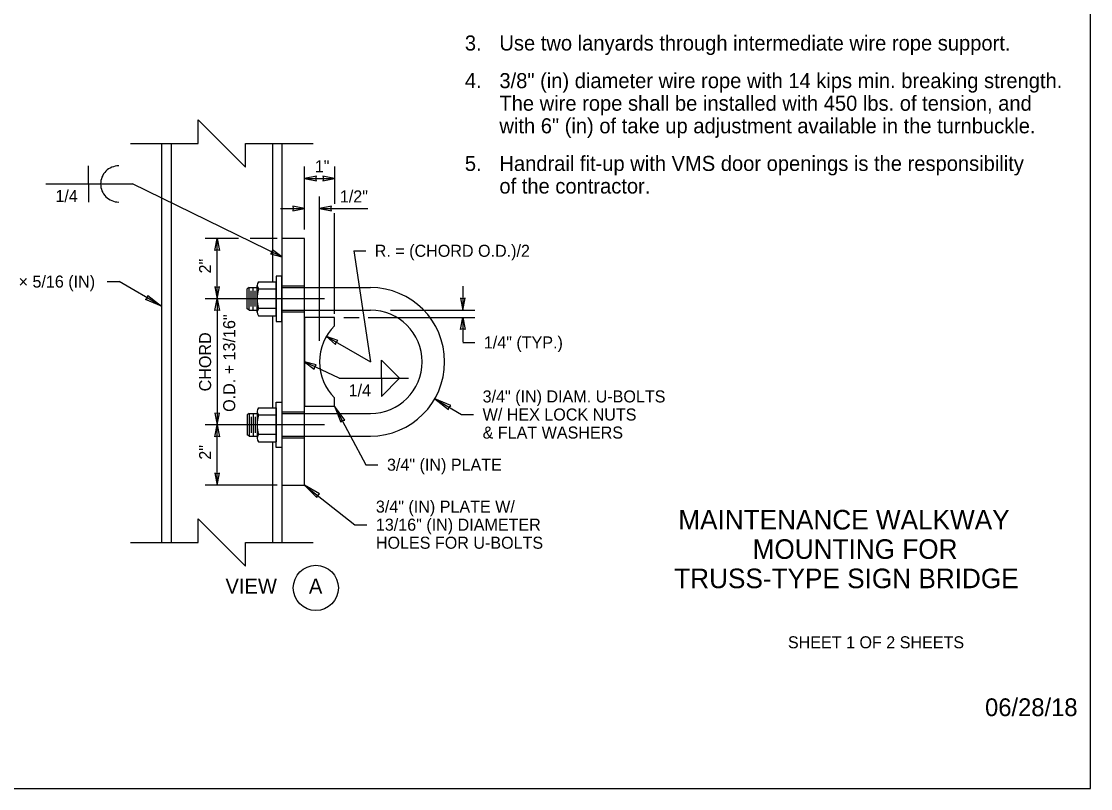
# Model space of a CAD drawing. Extents: x 99862 to 103151, y 100000 to 105076.
# Drawn here: x 101730 to 103151, y 100000 to 101019 of the extents above; entities that cross this region are included whole.
import ezdxf

# ---------------------------------------------------------------- set-up
doc = ezdxf.new("R2010")
doc.units = 0
for name, color, linetype in [('Level 1', 7, 'Continuous'), ('Level 15', 7, 'Continuous'), ('Level 2', 7, 'Continuous'), ('Level 20', 7, 'Continuous'), ('Level 36', 7, 'Continuous'), ('Level 4', 7, 'Continuous'), ('Level 6', 7, 'Continuous'), ('Level 62', 7, 'Continuous'), ('Level 9', 7, 'Continuous')]:
    doc.layers.add(name, color=color, linetype=linetype)

msp = doc.modelspace()

# ---------------------------------------------------------------- linework, layer by layer
at = {"layer": 'Level 1'}
msp.add_lwpolyline([(99862, 99999.5), (103151, 99999.5), (103151, 102075.5), (99862, 102075.5)], close=True, dxfattribs=at)
at = {"layer": 'Level 15'}
for p, q in [((102106.1, 100742.3), (102106.1, 100826.3)), ((102146.1, 100826.3), (102146.1, 100776.3)), ((102076.1, 100705.9), (101877.3, 100802.9)), ((102106.1, 100810.3), (102146.1, 100810.3)), ((102126.1, 100594.6), (102126.1, 100786.3)), ((102074.1, 100770.3), (102106.1, 100770.3)), ((102126.1, 100770.3), (102190, 100770.3)), ((102146.1, 100630.3), (102146.1, 100764.3)), ((102018.4, 100730.3), (101973.9, 100730.3)), ((101989.9, 100650.3), (101989.9, 100730.3)), ((102069.8, 100730.3), (102033.9, 100730.3)), ((102171.4, 100714.1), (102187.4, 100714.1)), ((102171.4, 100714.1), (102193.6, 100566.6)), ((101843.8, 100673.2), (101859.8, 100673.2)), ((101916.1, 100640.7), (101859.8, 100673.2)), ((102316.4, 100667.3), (102316.4, 100635.3)), ((102132.4, 100650.3), (101973.9, 100650.3)), ((101989.9, 100650.3), (101989.9, 100482.8)), ((102220.2, 100635.3), (102332.4, 100635.3)), ((102158.1, 100625.3), (102178.8, 100625.3)), ((102190.8, 100625.3), (102332.4, 100625.3)), ((102316.4, 100625.3), (102316.4, 100593.3)), ((102135.1, 100600.3), (102193.6, 100566.6)), ((102316.4, 100592.3), (102332.4, 100592.3)), ((102152.1, 100544.7), (102106.1, 100566.6)), ((102279.1, 100517.2), (102314.8, 100496.6)), ((102146.1, 100507.8), (102187.7, 100429.9)), ((102314.8, 100496.6), (102330.8, 100496.6)), ((102132.4, 100482.8), (101973.9, 100482.8)), ((101989.9, 100402.8), (101989.9, 100482.8)), ((102187.7, 100429.9), (102203.7, 100429.9)), ((102069.8, 100402.8), (101973.9, 100402.8)), ((102106.1, 100402.8), (102172.9, 100350.2)), ((102172.9, 100350.2), (102188.9, 100350.2))]:
    msp.add_line(p, q, dxfattribs=at)
for points in [[(101874.7, 100856.6), (101964.7, 100856.6), (101964.7, 100887.9), (102027.4, 100825.2), (102027.4, 100856.6), (102117.4, 100856.6)], [(101874.7, 100326.6), (101964.7, 100326.6), (101964.7, 100357.9), (102027.4, 100295.2), (102027.4, 100326.6), (102117.4, 100326.6)]]:
    msp.add_lwpolyline(points, dxfattribs=at)
for points in [[(102106.1, 100810.3), (102121.8, 100807.2), (102121.1, 100810.3), (102121.8, 100813.4)], [(102146.1, 100810.3), (102130.4, 100813.4), (102131.1, 100810.3), (102130.4, 100807.2)], [(102106.1, 100770.3), (102090.4, 100773.4), (102091.1, 100770.3), (102090.4, 100767.2)], [(102126.1, 100770.3), (102141.8, 100767.2), (102141.1, 100770.3), (102141.8, 100773.4)], [(101989.9, 100730.3), (101993, 100714.6), (101989.9, 100715.3), (101986.8, 100714.6)], [(102076.1, 100705.9), (102063.3, 100715.6), (102062.6, 100712.5), (102060.6, 100710.1)], [(101989.9, 100650.3), (101993, 100666), (101989.9, 100665.3), (101986.8, 100666)], [(101916.1, 100640.7), (101894.8, 100649.5), (101897.2, 100651.6), (101897.8, 100654.7)], [(101989.9, 100650.3), (101993, 100634.6), (101989.9, 100635.3), (101986.8, 100634.6)], [(102316.4, 100635.3), (102319.5, 100651), (102316.4, 100650.3), (102313.4, 100651)], [(102316.4, 100625.3), (102319.5, 100609.6), (102316.4, 100610.3), (102313.4, 100609.6)], [(102135.1, 100600.3), (102147.2, 100589.8), (102148.1, 100592.8), (102150.3, 100595.1)], [(102106.1, 100566.6), (102119, 100557), (102119.6, 100560.1), (102121.6, 100562.6)], [(102279.1, 100517.2), (102297.4, 100503.2), (102298, 100506.3), (102300.4, 100508.4)], [(102146.1, 100507.8), (102154.2, 100486.3), (102156.3, 100488.6), (102159.5, 100489.1)], [(101989.9, 100482.8), (101993, 100498.5), (101989.9, 100497.8), (101986.8, 100498.5)], [(101989.9, 100482.8), (101993, 100467.1), (101989.9, 100467.8), (101986.8, 100467.1)], [(101989.9, 100402.8), (101993, 100418.5), (101989.9, 100417.8), (101986.8, 100418.5)], [(102106.1, 100402.8), (102122.2, 100386.4), (102123.2, 100389.4), (102125.9, 100391)]]:
    msp.add_lwpolyline(points, close=True, dxfattribs=at)
at = {"layer": 'Level 2'}
for p, q in [((102146.1, 100625.3), (102106.1, 100625.3)), ((102146.1, 100614.5), (102146.1, 100625.3)), ((102146.1, 100507.8), (102146.1, 100518.6)), ((102106.1, 100507.8), (102146.1, 100507.8))]:
    msp.add_line(p, q, dxfattribs=at)
msp.add_lwpolyline([(102106.1, 100730.3), (102076.1, 100730.3), (102076.1, 100402.8), (102106.1, 100402.8)], close=True, dxfattribs=at)
msp.add_lwpolyline([(102106.1, 100625.3), (102106.1, 100507.8)], dxfattribs=at)
msp.add_arc((102193.6, 100566.6), 67.5, 134.7249, 225.2751, dxfattribs=at)
at = {"layer": 'Level 20'}
for p, q in [((101819, 100802.9), (101819, 100826.9)), ((101762.3, 100802.9), (101877.3, 100802.9)), ((101819, 100802.9), (101819, 100778.9)), ((102208.5, 100544.7), (102208.5, 100568.7)), ((102208.5, 100568.7), (102232.5, 100544.7)), ((102152.1, 100544.7), (102244.4, 100544.7)), ((102208.5, 100544.7), (102208.5, 100520.7)), ((102208.5, 100520.7), (102232.5, 100544.7))]:
    msp.add_line(p, q, dxfattribs=at)
for start, end in [(90.0239, 180.024), (179.976, 269.9761)]:
    msp.add_arc((101859, 100802.9), 24, start, end, dxfattribs=at)
at = {"layer": 'Level 36'}
for p, q in [((101928.6, 100856.6), (101928.6, 100326.6)), ((102063.6, 100856.6), (102063.6, 100672.8)), ((102076.1, 100667.6), (102106.1, 100667.6)), ((102076.1, 100665.3), (102106.1, 100665.3)), ((102076.1, 100635.3), (102106.1, 100635.3)), ((102076.1, 100633.1), (102106.1, 100633.1)), ((102063.6, 100627.8), (102063.6, 100505.3)), ((102076.1, 100500.1), (102106.1, 100500.1)), ((102076.1, 100497.8), (102106.1, 100497.8)), ((102063.6, 100460.3), (102063.6, 100326.6)), ((102076.1, 100467.8), (102106.1, 100467.8)), ((102076.1, 100465.6), (102106.1, 100465.6))]:
    msp.add_line(p, q, dxfattribs=at)
at = {"layer": 'Level 4'}
for p, q in [((102044.7, 100672.8), (102068.4, 100672.8)), ((102068.4, 100627.8), (102068.4, 100672.8)), ((102032.5, 100665.3), (102029.7, 100663.7)), ((102029.7, 100636.9), (102029.7, 100663.7)), ((102032.5, 100665.3), (102043.2, 100665.3)), ((102032.5, 100635.3), (102032.5, 100665.3)), ((102035.2, 100639.9), (102035.2, 100660.8)), ((102037.9, 100635.3), (102037.9, 100665.3)), ((102040.6, 100639.9), (102040.6, 100660.8)), ((102043.2, 100632.5), (102043.2, 100668.1)), ((102068.4, 100663.3), (102044.7, 100663.3)), ((102032.5, 100635.3), (102029.7, 100636.9)), ((102032.5, 100635.3), (102043.2, 100635.3)), ((102068.4, 100637.3), (102044.7, 100637.3)), ((102044.7, 100627.8), (102068.4, 100627.8)), ((102044.7, 100505.3), (102068.4, 100505.3)), ((102068.4, 100505.3), (102068.4, 100460.3)), ((102032.5, 100497.8), (102029.7, 100496.2)), ((102029.7, 100496.2), (102029.7, 100469.4)), ((102032.5, 100497.8), (102043.2, 100497.8)), ((102032.5, 100497.8), (102032.5, 100467.8)), ((102035.2, 100493.3), (102035.2, 100472.4)), ((102037.9, 100497.8), (102037.9, 100467.8)), ((102040.6, 100493.3), (102040.6, 100472.4)), ((102043.2, 100500.6), (102043.2, 100465.1)), ((102068.4, 100495.8), (102044.7, 100495.8)), ((102032.5, 100467.8), (102029.7, 100469.4)), ((102032.5, 100467.8), (102043.2, 100467.8)), ((102068.4, 100469.8), (102044.7, 100469.8)), ((102044.7, 100460.3), (102068.4, 100460.3))]:
    msp.add_line(p, q, dxfattribs=at)
for points in [[(102076.1, 100620.3), (102076.1, 100680.3), (102068.4, 100680.3), (102068.4, 100620.3)], [(102076.1, 100512.8), (102076.1, 100452.8), (102068.4, 100452.8), (102068.4, 100512.8)]]:
    msp.add_lwpolyline(points, close=True, dxfattribs=at)
for centre, radius, start, end in [((102051.5, 100668.1), 8.24, 144.7199, 215.2801), ((102099.9, 100650.3), 56.7, 166.7504, 193.2496), ((102051.5, 100632.6), 8.24, 144.7199, 215.2801), ((102051.5, 100500.6), 8.24, 144.7199, 215.2801), ((102099.9, 100482.8), 56.7, 166.7504, 193.2496), ((102051.5, 100465.1), 8.24, 144.7199, 215.2801)]:
    msp.add_arc(centre, radius, start, end, dxfattribs=at)
at = {"layer": 'Level 6'}
for p, q in [((101916.1, 100856.6), (101916.1, 100326.6)), ((102076.1, 100856.6), (102076.1, 100730.3)), ((102106.1, 100665.3), (102193.6, 100665.3)), ((102106.1, 100635.3), (102193.6, 100635.3)), ((102106.1, 100497.8), (102193.6, 100497.8)), ((102106.1, 100467.8), (102193.6, 100467.8)), ((102076.1, 100402.8), (102076.1, 100326.6))]:
    msp.add_line(p, q, dxfattribs=at)
for radius in [98.7, 68.7]:
    msp.add_arc((102193.6, 100566.6), radius, 270, 90, dxfattribs=at)
at = {"layer": 'Level 9'}
msp.add_circle((102121.1, 100266.2), 30, dxfattribs=at)

# ---------------------------------------------------------------- texts
at = {"layer": 'Level 15'}
msp.add_text('06/28/18', height=23.62, dxfattribs=at).set_placement((103010.7, 100095.8))
at = {"layer": 'Level 20'}
for s, height, p in [('3.', 20, (102319.2, 100980.2)), ('Use two lanyards through intermediate wire rope support.', 20, (102365.1, 100980.2)), ('4.', 20, (102319.2, 100930.2)), ('3/8" (in) diameter wire rope with 14 kips min. breaking strength.', 20, (102365.1, 100930.2)), ('The wire rope shall be installed with 450 lbs. of tension, and', 20, (102365.1, 100900.2)), ('with 6" (in) of take up adjustment available in the turnbuckle.', 20, (102365.1, 100870.2)), ('1"', 16, (102119.7, 100818.3)), ('5.', 20, (102319.2, 100820.2)), ('Handrail fit-up with VMS door openings is the responsibility', 20, (102365.1, 100820.2)), ('of the contractor. ', 20, (102365.1, 100790.2)), ('1/4', 16, (101774.9, 100778.9)), ('1/2"', 16, (102153, 100778.3)), ('R. = (CHORD O.D.)/2', 16, (102199.4, 100706.1)), ('TS6×4 × 5/16 (IN)', 16, (101656.4, 100665.2)), ('1/4" (TYP.)', 16, (102344.4, 100584.3)), ('1/4', 16, (102164.7, 100520.7)), ('3/4" (IN) DIAM. U-BOLTS', 16, (102342.8, 100512.6)), ('W/ HEX LOCK NUTS', 16, (102342.8, 100488.6)), ('& FLAT WASHERS', 16, (102342.8, 100464.6)), ('3/4" (IN) PLATE', 16, (102215.7, 100421.9)), ('3/4" (IN) PLATE W/', 16, (102200.9, 100366.2)), ('13/16" (IN) DIAMETER', 16, (102200.9, 100342.2)), ('HOLES FOR U-BOLTS', 16, (102200.9, 100318.2)), ('VIEW', 20, (102001, 100258.6)), ('A', 20, (102111.9, 100258.6))]:
    msp.add_text(s, height=height, dxfattribs=at).set_placement(p)
for s, p in [('2"', (101981.9, 100684)), ('O.D. + 13/16"', (102013.9, 100500.1)), ('CHORD', (101981.9, 100527.3)), ('2"', (101981.9, 100436.5))]:
    msp.add_text(s, height=16, rotation=90, dxfattribs=at).set_placement(p)
at = {"layer": 'Level 62'}
for s, height, p in [('MAINTENANCE WALKWAY', 26, (102602.9, 100343.8)), ('MOUNTING FOR', 26, (102701.7, 100304.8)), ('TRUSS-TYPE SIGN BRIDGE', 26, (102597.5, 100265.8)), ('SHEET 1 OF 2 SHEETS', 16, (102748.6, 100185.9))]:
    msp.add_text(s, height=height, dxfattribs=at).set_placement(p)

doc.saveas('drawing.dxf')
